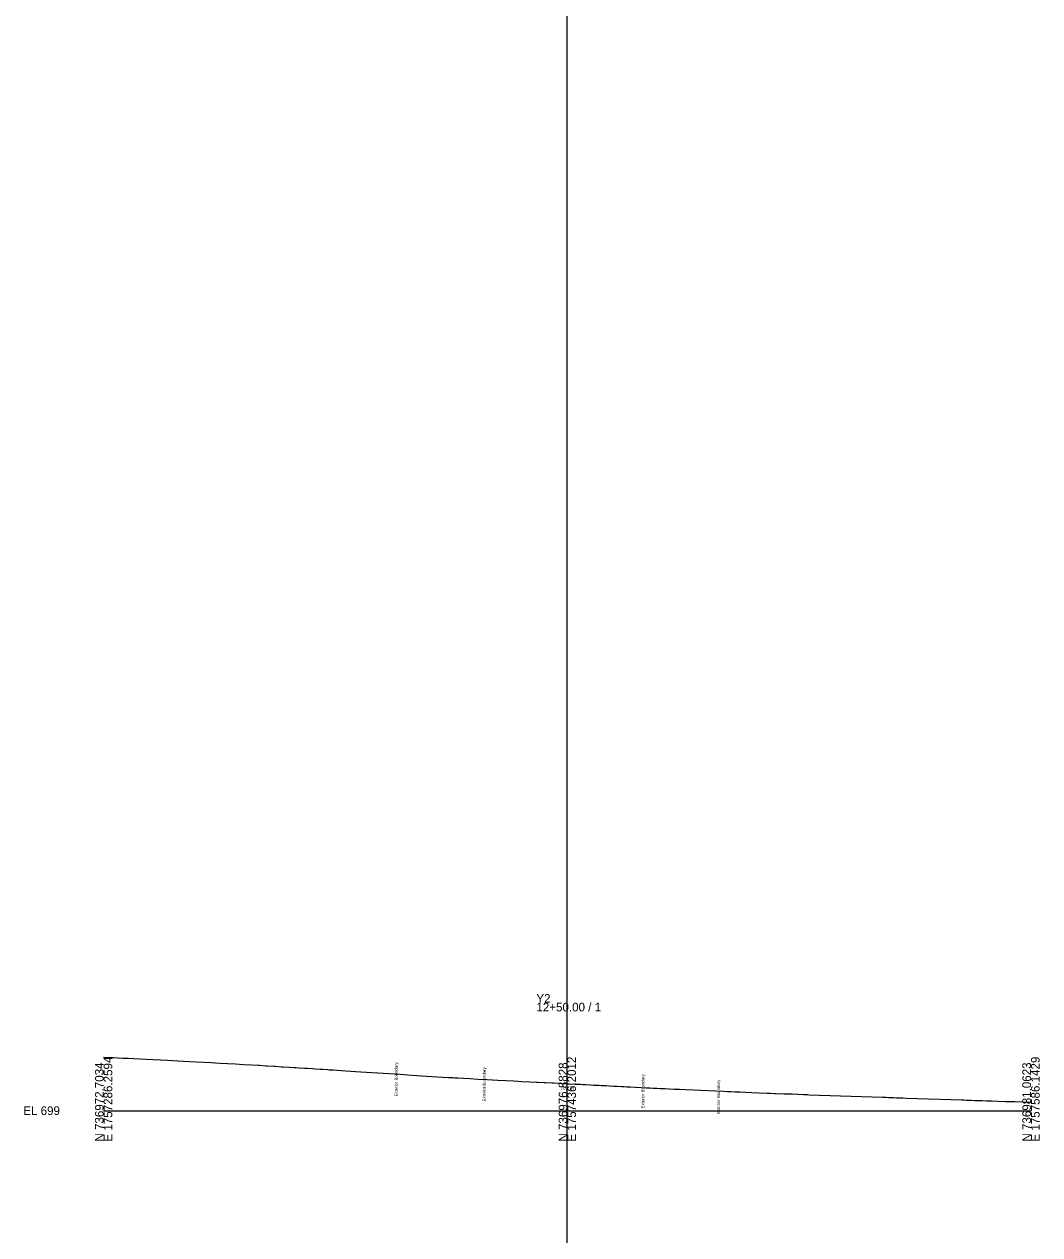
# Model space of a CAD drawing. Extents: x 24 to 1753, y -2082 to 299998921.
# Drawn here: x 24.3 to 352.8, y 2459.8 to 2851.6 of the extents above; entities that cross this region are included whole.
import ezdxf

# ---------------------------------------------------------------- set-up
doc = ezdxf.new("R2010")
doc.units = 0
for name, color, linetype in [('Default', 7, 'Continuous'), ('Exist Cross Section Cell', 7, 'Continuous'), ('Exist XS Center Line Elevation Label', 7, 'Continuous'), ('Exist XS Ground Line', 7, 'Continuous'), ('Scratch_Level_7', 7, 'Continuous')]:
    doc.layers.add(name, color=color, linetype=linetype)

msp = doc.modelspace()

# ---------------------------------------------------------------- linework, layer by layer
at = {"layer": 'Exist Cross Section Cell'}
for p, q in [((200, 1000), (200, 299998918)), ((200, 500), (200, 299998406)), ((200, 2500), (200, 2534.92)), ((50, 2500), (200, 2500)), ((200, 2500), (350, 2500))]:
    msp.add_line(p, q, dxfattribs=at)
at = {"layer": 'Exist XS Ground Line'}
msp.add_lwpolyline([(50, 2517.34), (51.62, 2517.26), (53.07, 2517.2), (54.6, 2517.12), (56.22, 2517.04), (57.94, 2516.95), (59.77, 2516.86), (61.72, 2516.77), (63.8, 2516.66), (70.62, 2516.32), (72.24, 2516.24), (73.97, 2516.15), (75.82, 2516.05), (77.81, 2515.95), (79.96, 2515.83), (82.27, 2515.7), (84.78, 2515.58), (87.56, 2515.43), (90.08, 2515.28), (92.65, 2515.14), (95.22, 2514.99), (97.79, 2514.83), (100.01, 2514.71), (100.37, 2514.68), (102.51, 2514.55), (102.94, 2514.52), (105.01, 2514.4), (105.51, 2514.36), (107.51, 2514.24), (108.09, 2514.21), (110.01, 2514.09), (111.51, 2513.99), (112.17, 2513.95), (113.1, 2513.89), (115.02, 2513.77), (115.8, 2513.72), (117.52, 2513.62), (118.38, 2513.56), (120.02, 2513.47), (120.95, 2513.41), (122.52, 2513.29), (123.01, 2513.26), (124.26, 2513.17), (125.57, 2513.09), (126.95, 2513.01), (128.4, 2512.91), (129.92, 2512.81), (131.52, 2512.7), (133.22, 2512.6), (145.94, 2511.77), (147.15, 2511.69), (148.44, 2511.61), (149.81, 2511.51), (151.27, 2511.43), (152.84, 2511.32), (154.52, 2511.22), (156.19, 2511.11), (157.85, 2510.99), (159.64, 2510.9), (161.58, 2510.79), (162.96, 2510.71), (163.64, 2510.67), (164.58, 2510.62), (166.44, 2510.51), (168.59, 2510.39), (171.1, 2510.24), (174.09, 2510.08), (177.55, 2509.89), (180.12, 2509.76), (182.69, 2509.61), (185.27, 2509.49), (187.84, 2509.36), (190.05, 2509.24), (190.41, 2509.23), (192.55, 2509.11), (192.98, 2509.09), (195.05, 2509), (195.56, 2508.97), (197.55, 2508.87), (198.13, 2508.84), (200.05, 2508.74), (200.7, 2508.7), (202.55, 2508.61), (204.3, 2508.53), (205.05, 2508.49), (205.85, 2508.44), (207.55, 2508.34), (208.42, 2508.3), (210.05, 2508.22), (210.99, 2508.18), (212.55, 2508.1), (213.56, 2508.06), (215.05, 2507.98), (216.14, 2507.93), (217.56, 2507.86), (218.24, 2507.83), (219.27, 2507.77), (220.38, 2507.72), (225.62, 2507.44), (226.65, 2507.39), (227.74, 2507.33), (228.92, 2507.26), (230.18, 2507.21), (231.54, 2507.15), (233, 2507.08), (234.59, 2507), (236.32, 2506.92), (238.21, 2506.83), (250.55, 2506.3), (251.68, 2506.25), (252.93, 2506.19), (254.32, 2506.12), (255.88, 2506.05), (257.64, 2505.99), (259.65, 2505.91), (261.95, 2505.82), (264.63, 2505.72), (265.58, 2505.68), (267.01, 2505.61), (267.59, 2505.59), (270.16, 2505.5), (272.74, 2505.4), (276.38, 2505.25), (276.7, 2505.24), (277.03, 2505.23), (277.39, 2505.21), (277.78, 2505.2), (278.19, 2505.18), (301.93, 2504.37), (302.63, 2504.35), (303.17, 2504.33), (303.91, 2504.3), (304.7, 2504.28), (305.55, 2504.25), (306.46, 2504.21), (307.45, 2504.18), (308.51, 2504.14), (309.67, 2504.1), (327.58, 2503.48), (328.24, 2503.46), (328.98, 2503.44), (329.79, 2503.41), (330.69, 2503.38), (331.7, 2503.34), (332.85, 2503.3), (334.15, 2503.26), (335.65, 2503.21), (337.38, 2503.15), (339.42, 2503.09), (341.85, 2503.01), (344.79, 2502.92), (350, 2502.76)], dxfattribs=at)

# ---------------------------------------------------------------- texts
at = {"layer": 'Default'}
msp.add_text('-', height=0.0001, dxfattribs=at).set_placement((50, 2500))
at = {"layer": 'Exist Cross Section Cell'}
for s, p in [('Y2', (190, 2534.92)), ('12+50.00 / 1', (190, 2532.12)), ('EL 699', (24, 2498.6))]:
    msp.add_text(s, height=2.8, dxfattribs=at).set_placement(p)
for s, p in [('N 736972.7034', (50, 2490)), ('E 1757286.2594', (52.8, 2490)), ('N 736976.8828', (200, 2490)), ('E 1757436.2012', (202.8, 2490)), ('N 736981.0623', (350, 2490)), ('E 1757586.1429', (352.8, 2490))]:
    msp.add_text(s, height=2.8, rotation=90, dxfattribs=at).set_placement(p)
at = {"layer": 'Exist XS Center Line Elevation Label'}
msp.add_text('707.74', height=1, dxfattribs=at).set_placement((197.86, 2506.74))
at = {"layer": 'Scratch_Level_7'}
for p in [(145.14, 2504.63), (173.63, 2503), (224.93, 2500.75), (249.37, 2498.95)]:
    msp.add_text('Exterior Boundary', height=1, rotation=90, dxfattribs=at).set_placement(p)

doc.saveas('drawing.dxf')
